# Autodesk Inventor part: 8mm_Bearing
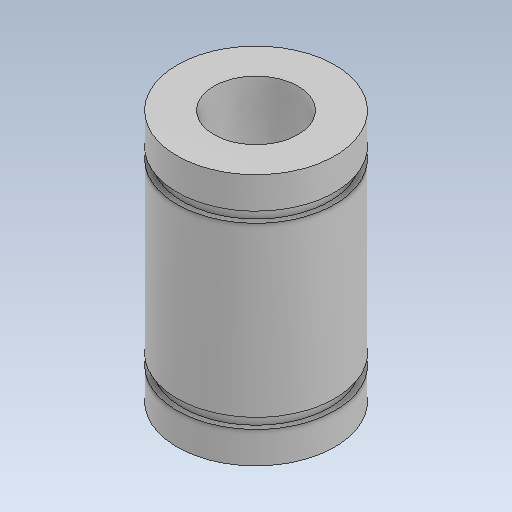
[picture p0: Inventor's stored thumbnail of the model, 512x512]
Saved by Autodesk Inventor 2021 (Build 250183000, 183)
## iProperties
Created: 2026-10
Part Number: 8mm_Bearing
Material: Generic
Document SubType Name: Modeling
Designer: hp
Density: 1 g/cm^3
Appearance: Default
Author: hp
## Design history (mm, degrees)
feature "Body1"
body "Solid1"
